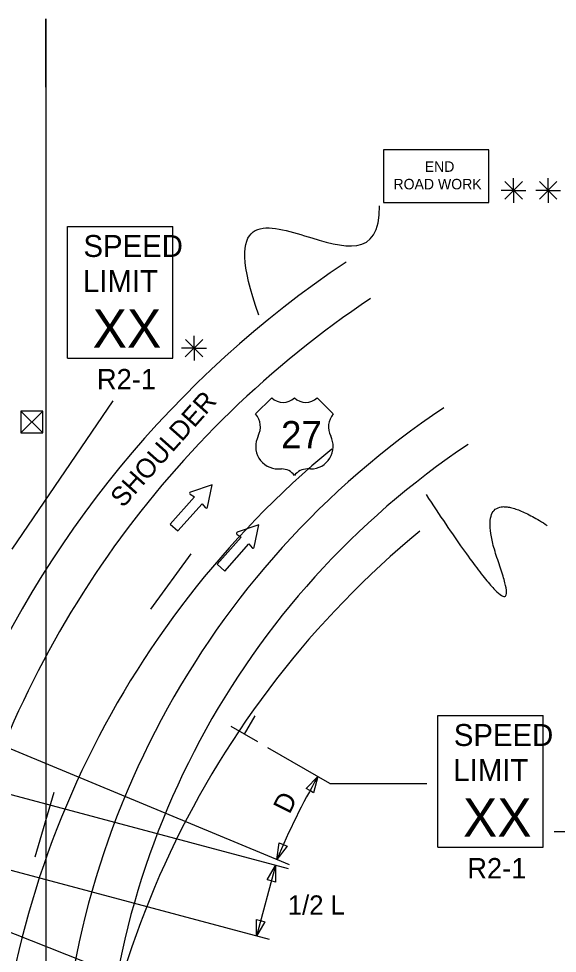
# Model space of a CAD drawing. Extents: x 16440 to 18464, y 5737 to 6974.
# Drawn here: x 16994.8 to 17191.2, y 6633.2 to 6974.1 of the extents above; entities that cross this region are included whole.
import ezdxf

# ---------------------------------------------------------------- set-up
doc = ezdxf.new("R2010")
doc.units = 0
for name, color, linetype in [('ALI_LEGAL_EX', 7, 'Continuous'), ('MT_SCRATCH_LEVEL_E', 7, 'Continuous'), ('PAVT_EDGE_EX', 7, 'Continuous'), ('TRAFFIC_SIGNS_PR', 7, 'Continuous'), ('TYPICAL_EX', 7, 'Continuous'), ('TYPICAL_TEXT_DIMEN_PR', 7, 'Continuous')]:
    doc.layers.add(name, color=color, linetype=linetype)

msp = doc.modelspace()

# ---------------------------------------------------------------- linework, layer by layer
at = {"layer": 'ALI_LEGAL_EX'}
for p, q in [((17004.68, 6974.12), (17004.68, 6155.98)), ((17004.68, 6891.53), (17004.68, 6027.61)), ((17007.7, 6691.9), (17000.71, 6668.24))]:
    msp.add_line(p, q, dxfattribs=at)
for points in [[(17004.68, 6949.12), (17004.68, 6974.12)], [(17043, 6758.79), (17057.75, 6778.98)]]:
    msp.add_lwpolyline(points, dxfattribs=at)
for centre in [(17325.51, 6555.03), (17357.65, 6525.15)]:
    msp.add_arc(centre, 340, 129.5666, 180, dxfattribs=at)
at = {"layer": 'MT_SCRATCH_LEVEL_E'}
for p, q in [((17065.34, 6804.16), (17057.46, 6801.48)), ((17063.63, 6795.99), (17065.34, 6804.16)), ((17058.9, 6799.7), (17050.1, 6789.79)), ((17057.36, 6800.64), (17058.9, 6799.7)), ((17052.89, 6787.3), (17061.7, 6797.21)), ((17061.7, 6797.21), (17062.82, 6795.8)), ((17050.1, 6789.79), (17052.89, 6787.3)), ((17082.42, 6789.5), (17074.54, 6786.82)), ((17080.72, 6781.33), (17082.42, 6789.5)), ((17075.99, 6785.04), (17067.18, 6775.13)), ((17074.45, 6785.99), (17075.99, 6785.04)), ((17069.98, 6772.65), (17078.78, 6782.56)), ((17078.78, 6782.56), (17079.9, 6781.14)), ((17067.18, 6775.13), (17069.98, 6772.65))]:
    msp.add_line(p, q, dxfattribs=at)
for centre, start, end in [((17057.61, 6801.04), 108.8028, 238.3418), ((17063.18, 6796.09), 218.4141, 348.1511), ((17074.7, 6786.38), 108.8028, 238.3418), ((17080.26, 6781.44), 218.4141, 348.1511)]:
    msp.add_arc(centre, 0.463, start, end, dxfattribs=at)
at = {"layer": 'PAVT_EDGE_EX'}
for radius, end in [(380, 157.5011), (364, 165.0045), (316, 180), (300, 180)]:
    msp.add_arc((17325.51, 6569.52), radius, 123.7854, end, dxfattribs=at)
at = {"layer": 'TRAFFIC_SIGNS_PR'}
for p, q in [((17012.67, 6898.36), (17051.07, 6898.36)), ((17012.67, 6850.36), (17012.67, 6898.36)), ((17051.07, 6850.36), (17051.07, 6898.36)), ((17012.67, 6850.36), (17051.07, 6850.36)), ((17147.68, 6719.98), (17186.08, 6719.98)), ((17147.68, 6671.98), (17147.68, 6719.98)), ((17186.08, 6671.98), (17186.08, 6719.98)), ((17147.68, 6671.98), (17186.08, 6671.98))]:
    msp.add_line(p, q, dxfattribs=at)
msp.add_lwpolyline([(17127.85, 6907.13), (17166.25, 6907.13), (17166.25, 6926.33), (17127.85, 6926.33)], close=True, dxfattribs=at)
at = {"layer": 'TYPICAL_EX'}
for p, q in [((17081.21, 6829.94), (17087.1, 6835.84)), ((17109.51, 6829.94), (17103.61, 6835.84)), ((17089.45, 6809.88), (17090.63, 6809.88)), ((17101.26, 6809.88), (17100.08, 6809.88))]:
    msp.add_line(p, q, dxfattribs=at)
for centre, radius, start, end in [((17091.23, 6840.13), 5.96, 226.1404, 313.8596), ((17099.48, 6840.13), 5.96, 226.1404, 313.8596), ((17075.62, 6825.22), 7.31, 333.0977, 40.1936), ((17115.09, 6825.22), 7.31, 139.8064, 206.9023), ((17089.47, 6818.13), 8.24, 152.6698, 269.9013), ((17101.25, 6818.13), 8.24, 270.0987, 27.3302), ((17090.65, 6803.98), 5.91, 37.1038, 90.1385), ((17100.07, 6803.98), 5.91, 89.8615, 142.8962)]:
    msp.add_arc(centre, radius, start, end, dxfattribs=at)
at = {"layer": 'TYPICAL_TEXT_DIMEN_PR'}
for p, q in [((17172.08, 6914.69), (17178.46, 6908.31)), ((17178.46, 6914.69), (17172.08, 6908.31)), ((17175.27, 6911.5), (17175.27, 6915.95)), ((17184.64, 6914.69), (17191.01, 6908.31)), ((17191.01, 6914.69), (17184.64, 6908.31)), ((17187.83, 6911.5), (17187.83, 6915.95)), ((17175.27, 6911.5), (17170.74, 6911.5)), ((17175.27, 6911.5), (17178.46, 6911.5)), ((17175.27, 6911.5), (17179.75, 6911.5)), ((17175.27, 6911.5), (17175.27, 6907)), ((17187.83, 6911.5), (17183.3, 6911.5)), ((17187.83, 6911.5), (17191.01, 6911.5)), ((17187.83, 6911.5), (17192.31, 6911.5)), ((17187.83, 6911.5), (17187.83, 6907)), ((17061.96, 6857.16), (17055.58, 6850.78)), ((17055.59, 6857.16), (17061.96, 6850.78)), ((17058.77, 6853.97), (17058.77, 6858.43)), ((17058.77, 6853.97), (17054.24, 6853.97)), ((17058.77, 6853.97), (17061.96, 6853.97)), ((17058.77, 6853.97), (17063.25, 6853.97)), ((17058.77, 6853.97), (17058.77, 6849.47)), ((16992.47, 6780.68), (17029.33, 6834.75)), ((16995.58, 6831.02), (17003.58, 6823.02)), ((16995.58, 6823.02), (17003.58, 6831.02)), ((17077.17, 6713.12), (17081.06, 6719.86)), ((17082.04, 6710.31), (17072.29, 6715.93)), ((17093.61, 6665.56), (16977.03, 6713.85)), ((17108.22, 6695.16), (17085.71, 6708.17)), ((17099.6, 6693.37), (17103.89, 6697.66)), ((17103.89, 6697.66), (17102.32, 6691.8)), ((17108.22, 6695.16), (17143.57, 6695.16)), ((17093.19, 6664), (16981.21, 6693.99)), ((17100.96, 6692.59), (17099.6, 6693.37)), ((17102.32, 6691.8), (17100.96, 6692.59)), ((17194.54, 6677.57), (17190.01, 6677.57)), ((17088.99, 6667.48), (17089.79, 6673.49)), ((17092.69, 6672.29), (17088.99, 6667.48)), ((17089.79, 6673.49), (17091.24, 6672.89)), ((17091.24, 6672.89), (17092.69, 6672.29)), ((17086.29, 6638.21), (16982.82, 6665.93)), ((17088.41, 6665.28), (17081.5, 6639.5)), ((17085.37, 6660.03), (17088.41, 6665.28)), ((17088.41, 6665.28), (17088.41, 6659.21)), ((17086.89, 6659.62), (17085.37, 6660.03)), ((17088.41, 6659.21), (17086.89, 6659.62)), ((16964.45, 6651.69), (17046.11, 6619.48)), ((17081.5, 6639.5), (17081.5, 6645.57)), ((17081.5, 6645.57), (17083.02, 6645.16)), ((17084.53, 6644.75), (17081.5, 6639.5)), ((17083.02, 6645.16), (17084.53, 6644.75))]:
    msp.add_line(p, q, dxfattribs=at)
msp.add_lwpolyline([(16995.58, 6831.02), (16995.58, 6823.02), (17003.58, 6823.02), (17003.58, 6831.02)], close=True, dxfattribs=at)
msp.add_arc((17325.51, 6569.52), 256, 149.9625, 157.5013, dxfattribs=at)
for points, degree in [([(17082.33, 6866.03), (17068.93, 6903.88), (17100.44, 6894.82), (17126.48, 6886.28), (17126.41, 6905.9)], 3), ([(17143.35, 6800.53), (17181.58, 6742.35), (17158.37, 6808.06), (17187.53, 6789.29)], 2)]:
    msp.add_open_spline(points, degree=degree, dxfattribs=at)

# ---------------------------------------------------------------- texts
at = {"layer": 'TRAFFIC_SIGNS_PR'}
for s, height, p in [('END', 3.831, (17142.85, 6918.26)), ('ROAD WORK', 3.831, (17131.46, 6911.87)), ('SPEED', 8, (17018.44, 6887.22)), ('LIMIT', 8, (17018.27, 6874.42)), ('XX', 14.031, (17021.78, 6854.12)), ('R2-1', 7.44, (17023.35, 6838.92)), ('SPEED', 8, (17153.45, 6708.85)), ('LIMIT', 8, (17153.28, 6696.05)), ('XX', 14.031, (17156.79, 6675.74)), ('R2-1', 7.44, (17158.36, 6660.54))]:
    msp.add_text(s, height=height, dxfattribs=at).set_placement(p)
at = {"layer": 'TYPICAL_EX'}
msp.add_text('27', height=10, dxfattribs=at).set_placement((17090.47, 6817.37))
at = {"layer": 'TYPICAL_TEXT_DIMEN_PR'}
for s, rotation, p in [('SHOULDER', 48.378, (17032.86, 6795.46)), ('D', 63.7334, (17093.58, 6683.72))]:
    msp.add_text(s, height=7, rotation=rotation, dxfattribs=at).set_placement(p)
msp.add_text('1/2 L', height=7, dxfattribs=at).set_placement((17092.94, 6647.35))

doc.saveas('drawing.dxf')
